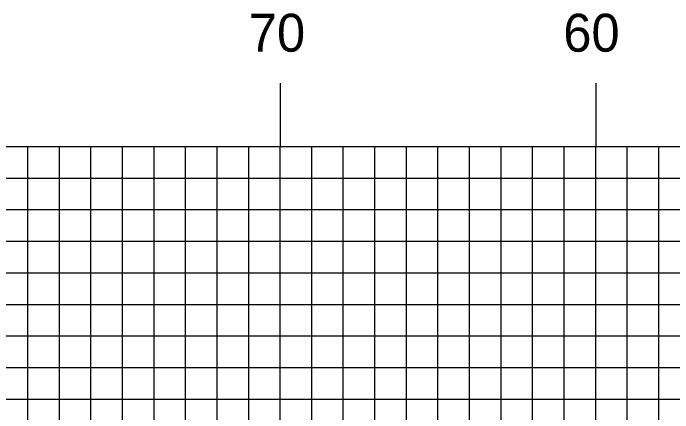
# Model space of a CAD drawing. Extents: x 1788943 to 1789287, y 442591 to 442811.
# Drawn here: x 1789030.69 to 1789051.6, y 442635.23 to 442647.88 of the extents above; entities that cross this region are included whole.
import ezdxf

# ---------------------------------------------------------------- set-up
doc = ezdxf.new("R2010")
doc.units = 0
for name, color, linetype in [('H_V ANNOTATION', 7, 'Continuous'), ('MAJOR', 7, 'Continuous'), ('MINOR', 7, 'Continuous')]:
    doc.layers.add(name, color=color, linetype=linetype)

msp = doc.modelspace()

# ---------------------------------------------------------------- linework, layer by layer
at = {"layer": 'MAJOR'}
for p, q in [((1789039.156, 442645.669), (1789039.156, 442643.665)), ((1789049.156, 442645.669), (1789049.156, 442643.665)), ((1788969.156, 442643.665), (1789249.156, 442643.665)), ((1788969.156, 442643.665), (1789249.156, 442643.665)), ((1789039.156, 442608.665), (1789039.156, 442643.665)), ((1789049.156, 442608.665), (1789049.156, 442643.665)), ((1788969.156, 442638.665), (1789249.156, 442638.665))]:
    msp.add_line(p, q, dxfattribs=at)
at = {"layer": 'MINOR'}
for p, q in [((1789031.156, 442608.665), (1789031.156, 442643.665)), ((1789032.156, 442608.665), (1789032.156, 442643.665)), ((1789033.156, 442608.665), (1789033.156, 442643.665)), ((1789034.156, 442608.665), (1789034.156, 442643.665)), ((1789035.156, 442608.665), (1789035.156, 442643.665)), ((1789036.156, 442608.665), (1789036.156, 442643.665)), ((1789037.156, 442608.665), (1789037.156, 442643.665)), ((1789038.156, 442608.665), (1789038.156, 442643.665)), ((1789040.156, 442608.665), (1789040.156, 442643.665)), ((1789041.156, 442608.665), (1789041.156, 442643.665)), ((1789042.156, 442608.665), (1789042.156, 442643.665)), ((1789043.156, 442608.665), (1789043.156, 442643.665)), ((1789044.156, 442608.665), (1789044.156, 442643.665)), ((1789045.156, 442608.665), (1789045.156, 442643.665)), ((1789046.156, 442608.665), (1789046.156, 442643.665)), ((1789047.156, 442608.665), (1789047.156, 442643.665)), ((1789048.156, 442608.665), (1789048.156, 442643.665)), ((1789050.156, 442608.665), (1789050.156, 442643.665)), ((1789051.156, 442608.665), (1789051.156, 442643.665)), ((1788969.156, 442642.665), (1789249.156, 442642.665)), ((1788969.156, 442641.665), (1789249.156, 442641.665)), ((1788969.156, 442640.665), (1789249.156, 442640.665)), ((1788969.156, 442639.665), (1789249.156, 442639.665)), ((1788969.156, 442637.665), (1789249.156, 442637.665)), ((1788969.156, 442636.665), (1789249.156, 442636.665)), ((1788969.156, 442635.665), (1789249.156, 442635.665))]:
    msp.add_line(p, q, dxfattribs=at)

# ---------------------------------------------------------------- texts
at = {"layer": 'H_V ANNOTATION'}
for s, p in [('70', (1789038.161, 442646.665)), ('60', (1789048.129, 442646.665))]:
    msp.add_text(s, height=1.2, dxfattribs=at).set_placement(p)

doc.saveas('drawing.dxf')
